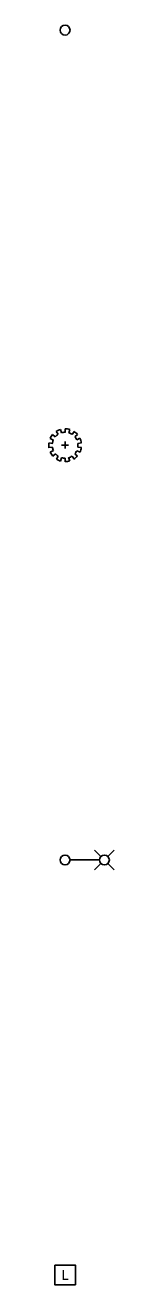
# Model space of a CAD drawing. Extents: x 98 to 2902, y -6 to 903.
# Drawn here: x 1098 to 1106, y 748.8 to 900.6 of the extents above; entities that cross this region are included whole.
import ezdxf

# ---------------------------------------------------------------- set-up
doc = ezdxf.new("R2010")
doc.units = 0
for name, color, linetype in [('V-POWR-POLE', 7, 'Continuous'), ('V-SITE-OTLN', 7, 'Continuous'), ('V-SITE-VEGE', 7, 'Continuous'), ('V-SSWR-DEVC', 7, 'Continuous')]:
    doc.layers.add(name, color=color, linetype=linetype)

msp = doc.modelspace()

# ---------------------------------------------------------------- linework, layer by layer
at = {"layer": 'V-POWR-POLE'}
msp.add_circle((1100, 900), 0.595, dxfattribs=at)
at = {"layer": 'V-SITE-OTLN'}
for p, q in [((1100.6, 800), (1104.17, 800)), ((1104.34, 800.42), (1103.57, 801.19)), ((1105.18, 800.42), (1105.95, 801.19)), ((1104.34, 799.58), (1103.57, 798.81)), ((1105.18, 799.58), (1105.95, 798.81))]:
    msp.add_line(p, q, dxfattribs=at)
for centre in [(1100, 800), (1104.76, 800)]:
    msp.add_circle(centre, 0.595, dxfattribs=at)
at = {"layer": 'V-SITE-VEGE'}
for p, q in [((1099.17, 851.3), (1098.93, 851.65)), ((1099.46, 851.89), (1099.56, 851.47)), ((1100, 851.53), (1100.01, 851.96)), ((1100.57, 851.88), (1100.45, 851.47)), ((1100.84, 851.29), (1101.08, 851.64)), ((1098.03, 850.25), (1098.46, 850.18)), ((1098.58, 850.61), (1098.19, 850.78)), ((1098.49, 851.26), (1098.81, 850.98)), ((1100, 850.42), (1100, 849.58)), ((1101.51, 851.27), (1101.19, 850.99)), ((1101.42, 850.62), (1101.8, 850.82)), ((1101.97, 850.25), (1101.54, 850.19)), ((1098.46, 849.76), (1098.04, 849.69)), ((1098.19, 849.16), (1098.58, 849.35)), ((1098.83, 848.96), (1098.5, 848.68)), ((1098.94, 848.3), (1099.15, 848.68)), ((1099.58, 850), (1100.42, 850)), ((1100.43, 848.49), (1100.56, 848.08)), ((1101.08, 848.31), (1100.85, 848.68)), ((1101.17, 848.95), (1101.5, 848.68)), ((1101.81, 849.15), (1101.41, 849.31)), ((1101.54, 849.75), (1101.97, 849.7)), ((1099.58, 848.48), (1099.46, 848.07)), ((1100, 847.99), (1100, 848.42))]:
    msp.add_line(p, q, dxfattribs=at)
for radius, start, end in [(1.98, 105.972, 122.5562), (1.56, 89.9461, 106.3473), (1.98, 73.2952, 89.5718), (1.98, 40.7122, 57.1166), (1.98, 172.27, 188.583), (1.98, 139.7777, 156.0738), (1.56, 156.0557, 172.7558), (1.56, 122.254, 140.086), (1.56, 57.451, 73.0843), (1.56, 24.4529, 40.4774), (1.56, 351.5431, 7.6203), (1.98, 7.9671, 24.8625), (1.98, 204.5394, 220.9852), (1.56, 188.0619, 204.0332), (1.56, 221.2062, 236.7795), (1.56, 285.9559, 303.0564), (1.98, 302.8434, 319.0222), (1.56, 318.6432, 334.5795), (1.98, 335.3123, 351.7042), (1.98, 237.6108, 254.1981), (1.56, 254.31, 270.043), (1.98, 270.0356, 286.342)]:
    msp.add_arc((1100, 849.98), radius, start, end, dxfattribs=at)
at = {"layer": 'V-SSWR-DEVC'}
msp.add_lwpolyline([(1098.75, 751.19), (1101.25, 751.19), (1101.25, 748.81), (1098.75, 748.81)], close=True, dxfattribs=at)

# ---------------------------------------------------------------- texts
msp.add_text('L', height=1.19, dxfattribs=at).set_placement((1099.57, 749.4))

doc.saveas('drawing.dxf')
